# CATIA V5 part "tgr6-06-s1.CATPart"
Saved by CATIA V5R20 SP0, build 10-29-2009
Part number: TGR6-06-S1
Revision: 1
Definition: design
Nomenclature: TGR6-06-S1
Source: made
Description: NOT SPECIFIED
Bounding box of the stored display mesh (mm): x -3 to 3, y -6 to 0, z -17 to 0.6
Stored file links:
  C:\Users\Raffaele\Desktop\3D X SITO CF\I-MOLD\TGR-S1\tgr6-s1.step\tgr6-06-s1.CATPart
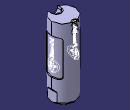
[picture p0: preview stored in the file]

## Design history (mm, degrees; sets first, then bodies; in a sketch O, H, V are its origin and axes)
Set1
  DatumCurve1 "COMPOSITE_CURVE #4480"
  DatumCurve2 "COMPOSITE_CURVE #4636"
  DatumCurve3 "COMPOSITE_CURVE #4697"
  DatumCurve4 "COMPOSITE_CURVE #4928"
  DatumCurve5 "COMPOSITE_CURVE #4955"
  DatumCurve6 "COMPOSITE_CURVE #5013"
  DatumCurve7 "COMPOSITE_CURVE #5066"
  DatumCurve8 "COMPOSITE_CURVE #5093"
  DatumCurve9 "COMPOSITE_CURVE #5169"
  DatumCurve10 "COMPOSITE_CURVE #5208"
  DatumCurve11 "COMPOSITE_CURVE #5261"
  DatumCurve12 "COMPOSITE_CURVE #5416"
  DatumCurve13 "COMPOSITE_CURVE #5477"
  DatumCurve14 "COMPOSITE_CURVE #5708"
  DatumCurve15 "COMPOSITE_CURVE #5735"
  DatumCurve16 "COMPOSITE_CURVE #5793"
  DatumCurve17 "COMPOSITE_CURVE #5846"
  DatumCurve18 "COMPOSITE_CURVE #5873"
  DatumCurve19 "COMPOSITE_CURVE #5949"
  DatumCurve20 "COMPOSITE_CURVE #5988"
  DatumSurface1 "OPEN_SHELL #4355"
  DatumSurface2 "OPEN_SHELL #4421"
Body1 "MANIFOLD_SOLID_BREP #4422" (main body)
  Solid1: solid without history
